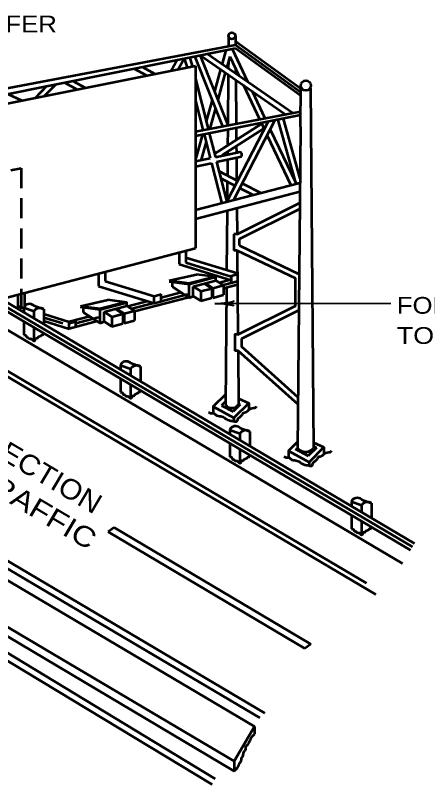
# Model space of a CAD drawing. Extents: x -68 to 612, y -58 to 382.
# Drawn here: x 477.3 to 538.8, y 172.1 to 286.9 of the extents above; entities that cross this region are included whole.
import ezdxf
from ezdxf.enums import TextEntityAlignment as Align

# ---------------------------------------------------------------- set-up
doc = ezdxf.new("R2010")
doc.units = 0
doc.linetypes.add('MEDIUM_DASHED', pattern=[4.5, 3, -1.5])
doc.layers.add('1', color=7, linetype='Continuous', lineweight=53)

msp = doc.modelspace()

# ---------------------------------------------------------------- linework, layer by layer
at = {"layer": '1'}
for p, q in [((509.106, 283.812), (509.093, 282.285)), ((510.118, 283.821), (510.13, 282.482)), ((510.125, 283.04), (519.888, 275.962)), ((510.13, 282.482), (519.883, 275.411)), ((468.152, 273.581), (510.134, 281.979)), ((508.716, 281.695), (508.143, 279.635)), ((509.628, 281.877), (511.946, 276.992)), ((510.134, 281.979), (519.879, 274.914)), ((500.527, 278.623), (501.452, 280.242)), ((503.258, 280.68), (503.665, 279.328)), ((504.089, 280.666), (508.246, 270.183)), ((504.833, 280.961), (508.99, 270.478)), ((504.881, 280.928), (517.578, 272.104)), ((505.969, 281.145), (518.679, 272.313)), ((509.281, 280.742), (508.839, 279.151)), ((509.281, 280.742), (510.625, 277.91)), ((474.259, 273.368), (504.159, 279.349)), ((494.963, 278.944), (496.878, 277.893)), ((496.181, 279.188), (498.097, 278.137)), ((504.159, 279.349), (504.159, 252.141)), ((509.073, 279.992), (509.064, 278.995)), ((507.916, 278.819), (506.995, 275.509)), ((508.612, 278.335), (507.483, 274.279)), ((509.056, 278.026), (508.99, 270.478)), ((510.161, 278.888), (510.167, 278.229)), ((481.631, 274.843), (483.353, 276.621)), ((484.602, 276.871), (486.518, 275.82)), ((485.821, 277.115), (487.737, 276.064)), ((504.159, 277.393), (506.065, 269.924)), ((510.175, 277.248), (510.232, 270.713)), ((480.249, 274.566), (481.972, 276.345)), ((511.315, 276.457), (513.726, 271.375)), ((512.636, 275.539), (514.538, 271.529)), ((519.838, 270.238), (519.892, 276.394)), ((521.317, 276.067), (521.786, 222.273)), ((476.073, 275.165), (478.208, 274.158)), ((504.159, 274.161), (505.278, 269.775)), ((506.64, 274.234), (505.766, 271.095)), ((504.159, 269.563), (519.858, 272.536)), ((504.159, 268.896), (519.854, 272.036)), ((507.128, 273.003), (506.282, 269.965)), ((508.843, 259.037), (515.059, 271.077)), ((509.904, 259.346), (516.063, 271.277)), ((519.124, 261.862), (516.526, 271.242)), ((519.771, 262.525), (517.297, 271.455)), ((507.016, 266.199), (514.042, 270.708)), ((508.166, 265.987), (514.387, 269.98)), ((508.984, 269.861), (508.963, 267.449)), ((510.237, 270.112), (510.253, 268.277)), ((513.97, 270.859), (514.438, 269.873)), ((515.331, 269.858), (519.124, 261.862)), ((519.838, 270.238), (519.74, 258.989)), ((505.213, 269.107), (504.231, 265.58)), ((505.437, 269.152), (506.353, 265.561)), ((506.222, 269.309), (507.136, 265.727)), ((514.869, 268.964), (518.401, 261.519)), ((505.733, 267.992), (505.002, 265.365)), ((507.136, 265.727), (510.838, 266.511)), ((508.955, 266.493), (508.952, 266.112)), ((510.262, 267.332), (510.27, 266.391)), ((504.159, 265.097), (506.353, 265.561)), ((507.321, 265.003), (511.009, 265.817)), ((508.945, 265.362), (508.924, 262.96)), ((510.276, 265.655), (510.306, 262.244)), ((504.159, 264.306), (506.54, 264.831)), ((506.54, 264.831), (508.077, 258.806)), ((507.321, 265.003), (508.843, 259.037)), ((507.677, 263.606), (510.458, 262.165)), ((504.159, 257.876), (519.765, 261.869)), ((507.942, 262.568), (510.091, 261.454)), ((508.916, 262.063), (508.89, 259.087)), ((511.169, 261.797), (513.916, 260.373)), ((504.159, 256.526), (519.754, 260.603)), ((510.802, 261.086), (512.752, 260.075)), ((519.74, 258.989), (519.419, 222.273)), ((508.879, 257.76), (508.801, 248.9)), ((510.731, 253.529), (519.731, 257.99)), ((509.897, 254.246), (509.897, 251.803)), ((510.376, 254.246), (509.897, 254.246)), ((453.651, 253.163), (535.086, 205.073)), ((510.731, 252.53), (510.731, 253.529)), ((510.731, 252.53), (519.646, 248.272)), ((474.259, 244.326), (504.159, 252.141)), ((501.708, 251.5), (501.708, 249.762)), ((502.708, 251.762), (502.708, 249.979)), ((510.397, 251.803), (509.897, 251.803)), ((510.397, 251.803), (519.113, 247.641)), ((510.397, 251.803), (510.506, 239.268)), ((502.708, 250.763), (510.427, 248.403)), ((501.708, 249.762), (509.358, 247.423)), ((502.708, 249.979), (509.505, 247.901)), ((489.677, 248.356), (489.677, 246.486)), ((490.677, 248.617), (490.677, 247.226)), ((500.248, 247.289), (504.339, 248.221)), ((510.429, 248.189), (509.505, 247.949)), ((468.381, 247.174), (536.273, 207.082)), ((469.138, 247.372), (536.555, 207.56)), ((469.96, 247.587), (536.862, 208.08)), ((490.677, 247.226), (498.016, 244.982)), ((500.232, 247.165), (503.21, 246.784)), ((500.248, 247.289), (503.226, 246.908)), ((500.728, 246.352), (500.728, 247.102)), ((503.178, 246.905), (506.885, 247.88)), ((503.21, 244.747), (503.21, 246.784)), ((503.821, 246.428), (507.21, 247.32)), ((505.469, 246.861), (506.611, 246.138)), ((505.621, 246.901), (506.763, 246.178)), ((507.21, 247.32), (507.21, 247.837)), ((509.379, 247.4), (507.75, 246.978)), ((509.505, 246.916), (508.329, 246.611)), ((509.505, 247.901), (509.505, 246.901)), ((510.438, 247.158), (509.505, 246.916)), ((489.677, 246.486), (498.016, 243.937)), ((500.728, 246.352), (503.21, 244.747)), ((503.821, 244.99), (503.821, 246.428)), ((504.963, 245.705), (506.611, 246.138)), ((506.611, 246.138), (506.611, 244.7)), ((506.763, 246.178), (508.352, 246.597)), ((506.763, 246.178), (506.763, 244.74)), ((510.442, 246.643), (508.352, 246.101)), ((508.778, 246.211), (508.626, 228.787)), ((477.645, 245.211), (477.645, 243.049)), ((478.645, 245.472), (478.645, 243.469)), ((503.188, 244.762), (495.078, 242.659)), ((498.016, 244.982), (499.016, 245.252)), ((498.016, 243.947), (498.016, 244.982)), ((502.048, 245.499), (499.016, 244.713)), ((499.016, 244.196), (499.016, 245.252)), ((502.976, 245.223), (499.016, 244.196)), ((504.963, 244.267), (506.611, 244.7)), ((506.763, 244.74), (508.352, 245.159)), ((457.006, 244.201), (531.083, 200.457)), ((458.025, 244.467), (529.679, 202.154)), ((477.645, 243.506), (478.645, 243.201)), ((480.01, 243.573), (481.51, 243.029)), ((486.958, 243.367), (489.936, 242.986)), ((486.974, 243.491), (491.065, 244.422)), ((486.974, 243.491), (489.952, 243.11)), ((489.904, 243.107), (493.61, 244.082)), ((490.547, 242.629), (493.936, 243.521)), ((493.936, 243.521), (493.936, 244.038)), ((497.101, 244.216), (494.077, 243.432)), ((498.016, 243.937), (494.656, 243.065)), ((498.016, 243.947), (499.132, 244.248)), ((478.51, 243.256), (480.01, 242.712)), ((478.51, 243.256), (478.51, 242.579)), ((480.01, 242.712), (480.01, 241.693)), ((481.51, 243.029), (481.51, 240.807)), ((481.51, 242.325), (485.318, 241.161)), ((487.454, 242.554), (487.454, 243.304)), ((487.454, 242.554), (489.936, 240.949)), ((489.936, 240.949), (489.936, 242.986)), ((490.547, 241.191), (490.547, 242.629)), ((491.688, 241.906), (493.336, 242.34)), ((492.194, 243.063), (493.336, 242.34)), ((492.347, 243.103), (493.489, 242.38)), ((493.336, 242.34), (493.336, 240.902)), ((493.489, 242.38), (495.078, 242.798)), ((493.489, 242.38), (493.489, 240.942)), ((511.061, 238.65), (519.599, 242.882)), ((478.51, 241.233), (478.51, 239.215)), ((481.51, 241.279), (485.296, 240.122)), ((489.521, 241.217), (485.296, 240.122)), ((485.296, 240.122), (485.296, 241.122)), ((488.38, 241.955), (485.318, 241.16)), ((486.296, 241.122), (486.267, 241.372)), ((489.678, 241.775), (486.296, 240.898)), ((493.489, 240.942), (495.078, 241.36)), ((480.01, 240.347), (480.01, 238.316)), ((491.688, 240.468), (493.336, 240.902)), ((481.51, 239.462), (481.51, 239.215)), ((510.528, 236.804), (510.028, 236.804)), ((519.476, 228.805), (510.528, 236.804)), ((510.528, 236.804), (510.598, 228.804)), ((423.405, 235.418), (513.778, 182.05)), ((424.768, 235.774), (514.52, 182.773)), ((421.36, 234.883), (512.987, 180.775)), ((492.948, 234.685), (494.448, 234.141)), ((492.948, 234.685), (492.948, 234.008)), ((494.448, 235.002), (495.948, 234.459)), ((495.948, 234.459), (495.948, 232.236)), ((494.448, 234.141), (494.448, 233.122)), ((411.694, 232.357), (509.936, 174.113)), ((413.181, 232.745), (509.936, 175.609)), ((492.948, 232.662), (492.948, 230.644)), ((408.38, 231.491), (506.63, 172.091)), ((409.73, 231.843), (507.099, 172.976)), ((494.448, 231.777), (494.448, 229.745)), ((495.948, 230.891), (495.948, 230.644)), ((506.821, 228.503), (509.912, 226.817)), ((508.63, 229.252), (508.06, 228.681)), ((508.06, 228.681), (509.778, 227.744)), ((510.825, 228.791), (509.778, 227.744)), ((510.597, 228.894), (510.825, 228.791)), ((512.123, 229.028), (512.123, 228.028)), ((509.912, 226.817), (509.912, 226.332)), ((509.273, 225.016), (510.773, 224.473)), ((509.273, 225.016), (509.273, 224.339)), ((510.773, 225.334), (512.273, 224.79)), ((510.773, 224.473), (510.773, 223.453)), ((512.273, 224.79), (512.273, 222.568)), ((509.273, 222.994), (509.273, 220.975)), ((521.779, 223.123), (523.338, 222.42)), ((510.773, 222.108), (510.773, 220.076)), ((518.035, 221.895), (521.126, 220.209)), ((519.055, 222.193), (520.993, 221.136)), ((522.216, 222.359), (520.993, 221.136)), ((523.338, 222.42), (521.126, 220.209)), ((521.783, 222.596), (522.216, 222.359)), ((523.338, 222.42), (523.338, 221.42)), ((512.273, 221.222), (512.273, 220.975)), ((521.126, 220.209), (521.126, 219.724)), ((528.942, 214.637), (530.442, 214.094)), ((527.442, 214.32), (528.942, 213.776)), ((527.442, 214.32), (527.442, 213.643)), ((528.942, 213.776), (528.942, 212.757)), ((530.442, 214.094), (530.442, 211.871)), ((527.442, 212.297), (527.442, 210.279)), ((528.942, 211.412), (528.942, 209.38)), ((492.009, 210.457), (491.141, 209.809)), ((492.009, 210.457), (521.373, 193.036)), ((530.442, 210.526), (530.442, 210.279)), ((491.141, 209.809), (520.505, 192.388)), ((521.373, 193.036), (520.505, 192.388)), ((512.987, 180.775), (509.936, 175.609)), ((512.987, 180.775), (512.987, 179.602)), ((509.936, 175.609), (509.936, 174.156))]:
    msp.add_line(p, q, dxfattribs=at)
at = {"layer": '1', "linetype": 'MEDIUM_DASHED'}
for p, q in [((478.145, 264.087), (478.145, 242.831)), ((478.145, 242.831), (478.51, 242.719)), ((481.51, 241.802), (485.172, 240.682))]:
    msp.add_line(p, q, dxfattribs=at)
at = {"layer": '1', "lineweight": 35}
msp.add_line((507.06, 243.87), (533.354, 243.87), dxfattribs=at)
at = {"layer": '1'}
for points in [[(359.251, 253.915), (359.997, 254.047), (510.13, 282.482)], [(501.567, 278.831), (502.492, 280.45), (502.899, 279.097)], [(510.342, 258.143), (510.376, 254.246), (519.739, 258.887)], [(503.21, 246.784), (507.21, 247.837), (504.339, 248.221)], [(507.21, 247.32), (508.352, 246.597), (508.352, 245.159)], [(510.463, 239.247), (519.113, 243.534), (519.113, 247.641)], [(503.821, 246.428), (504.963, 245.705), (504.963, 244.267)], [(503.21, 244.747), (503.821, 244.99), (504.963, 244.267)], [(489.936, 242.986), (493.936, 244.038), (491.065, 244.422)], [(493.936, 243.521), (495.078, 242.798), (495.078, 241.36)], [(490.547, 242.629), (491.688, 241.906), (491.688, 240.468)], [(486.296, 240.381), (486.296, 241.122), (485.319, 240.875)], [(489.936, 240.949), (490.547, 241.191), (491.688, 240.468)], [(510.463, 239.247), (510.028, 239.247), (510.028, 236.804)], [(519.486, 229.87), (511.061, 237.4), (511.061, 238.65)], [(508.639, 230.322), (506.821, 228.503), (506.821, 227.503)], [(510.59, 229.72), (512.123, 229.028), (509.912, 226.817)], [(519.428, 223.288), (518.035, 221.895), (518.035, 220.895)]]:
    msp.add_lwpolyline(points, dxfattribs=at)
at = {"layer": '1', "linetype": 'MEDIUM_DASHED'}
msp.add_lwpolyline([(375.294, 244.216), (392.667, 247.516), (478.145, 264.087)], dxfattribs=at)
at = {"layer": '1'}
for centre, radius in [((509.606, 283.812), 0.5), ((520.642, 276.394), 0.75)]:
    msp.add_circle(centre, radius, dxfattribs=at)
for centre, radius, start, end in [((510.583, 266.08), 0.501, 328.33099, 59.40133), ((479.379, 242.855), 0.957, 48.69365, 155.19657), ((480.928, 242.078), 1.115, 58.52834, 145.36189), ((493.817, 234.284), 0.957, 48.69365, 155.19657), ((495.366, 233.507), 1.115, 58.52834, 145.36189), ((509.606, 229.506), 1.215, 216.25079, 324.74685), ((510.141, 224.615), 0.957, 48.69365, 155.19657), ((511.69, 223.839), 1.115, 58.52834, 145.36189), ((520.603, 223.295), 1.564, 220.82266, 319.17734), ((528.31, 213.919), 0.957, 48.69365, 155.19657), ((529.859, 213.142), 1.115, 58.52834, 145.36189)]:
    msp.add_arc(centre, radius, start, end, dxfattribs=at)
at = {"layer": '1', "lineweight": 40}
for centre, major_axis, ratio, start_param, end_param in [((508.18, 243.659), (-1.756, 0.176), 0.07063, 3.1407148, 5.41811), ((508.151, 244.147), (-1.786, -0.156), 0.122415, 0.8963533, 3.1415927)]:
    msp.add_ellipse(centre, major_axis=major_axis, ratio=ratio, start_param=start_param, end_param=end_param, dxfattribs=at)
at = {"layer": '1'}
for points in [[(478.51, 239.215), (478.873, 239.041), (478.873, 238.95), (479.009, 238.859), (479.054, 238.859), (479.235, 238.724), (479.281, 238.678), (479.688, 238.588), (480.01, 238.316), (480.232, 238.406), (480.232, 238.542), (480.232, 238.633), (480.595, 238.724), (480.64, 238.814), (480.821, 238.95), (480.912, 238.995), (481.184, 239.131), (481.274, 239.222), (481.365, 239.267), (481.51, 239.215)], [(492.948, 230.644), (493.311, 230.47), (493.311, 230.379), (493.447, 230.289), (493.492, 230.289), (493.673, 230.153), (493.719, 230.107), (494.127, 230.017), (494.448, 229.745), (494.67, 229.835), (494.67, 229.971), (494.67, 230.062), (495.033, 230.153), (495.078, 230.243), (495.259, 230.379), (495.35, 230.425), (495.622, 230.561), (495.712, 230.651), (495.803, 230.697), (495.948, 230.644)], [(506.121, 227.656), (506.633, 227.491), (506.834, 227.509), (506.962, 227.454), (507.347, 227.18), (507.768, 227.088), (508.115, 227.015), (508.426, 226.887), (508.591, 226.74), (508.847, 226.612), (509.177, 226.447), (509.305, 226.411), (509.616, 226.356), (509.927, 226.319), (510.165, 226.264), (510.348, 226.319), (510.476, 226.557), (510.623, 226.832), (510.714, 226.887), (510.915, 227.052), (511.025, 227.161), (511.19, 227.381), (511.354, 227.582), (511.629, 227.674), (511.922, 227.82), (512.087, 227.985), (512.215, 228.095), (512.416, 228.205), (512.855, 228.315), (513.13, 228.37), (513.258, 228.534)], [(517.335, 221.047), (517.848, 220.883), (518.049, 220.901), (518.177, 220.846), (518.561, 220.571), (518.982, 220.48), (519.33, 220.407), (519.641, 220.279), (519.806, 220.132), (520.062, 220.004), (520.391, 219.839), (520.519, 219.803), (520.831, 219.748), (521.142, 219.711), (521.38, 219.656), (521.563, 219.711), (521.691, 219.949), (521.837, 220.224), (521.929, 220.279), (522.13, 220.443), (522.24, 220.553), (522.404, 220.773), (522.569, 220.974), (522.844, 221.066), (523.136, 221.212), (523.301, 221.377), (523.429, 221.487), (523.631, 221.597), (524.07, 221.707), (524.344, 221.761), (524.472, 221.926)], [(509.273, 220.975), (509.635, 220.801), (509.635, 220.711), (509.771, 220.62), (509.816, 220.62), (509.998, 220.484), (510.043, 220.439), (510.451, 220.348), (510.773, 220.076), (510.994, 220.167), (510.994, 220.303), (510.994, 220.393), (511.357, 220.484), (511.402, 220.575), (511.583, 220.711), (511.674, 220.756), (511.946, 220.892), (512.037, 220.983), (512.127, 221.028), (512.273, 220.975)], [(527.442, 210.279), (527.804, 210.105), (527.804, 210.014), (527.94, 209.924), (527.985, 209.924), (528.167, 209.788), (528.212, 209.742), (528.62, 209.652), (528.942, 209.38), (529.163, 209.47), (529.163, 209.606), (529.163, 209.697), (529.526, 209.788), (529.571, 209.878), (529.752, 210.014), (529.843, 210.06), (530.115, 210.196), (530.206, 210.286), (530.296, 210.332), (530.442, 210.279)], [(509.936, 174.156), (510.271, 174.423), (510.331, 174.482), (510.48, 174.691), (510.659, 175.049), (510.808, 175.347), (510.927, 175.526), (511.017, 175.735), (511.017, 176.033), (511.166, 176.242), (511.315, 176.66), (511.494, 177.137), (511.702, 177.375), (511.672, 177.733), (511.971, 178.061), (512.12, 178.33), (512.358, 178.718), (512.507, 179.076), (512.987, 179.602)]]:
    msp.add_spline(points, degree=3, dxfattribs=at)

# ---------------------------------------------------------------- texts
for s, width, p in [('FOR CONNECTION DETAILS REFER', 1.15, (417.251, 284.329)), ('FOR FIXTURE DETAILS REFER', 1.15, (534.221, 242.351)), ('TO STANDARD SHEET TE6-3C.', 1.2, (534.221, 237.851))]:
    msp.add_text(s, height=2.5, dxfattribs=dict(at, width=width)).set_placement(p)
for s, width, p in [('DIRECTION', 1.1, (478.585, 218.557)), ('OF TRAFFIC', 1.2, (476.034, 214.257))]:
    msp.add_text(s, height=3, rotation=329.321, dxfattribs=dict(at, width=width)).set_placement(p, align=Align.CENTER)

doc.saveas('drawing.dxf')
